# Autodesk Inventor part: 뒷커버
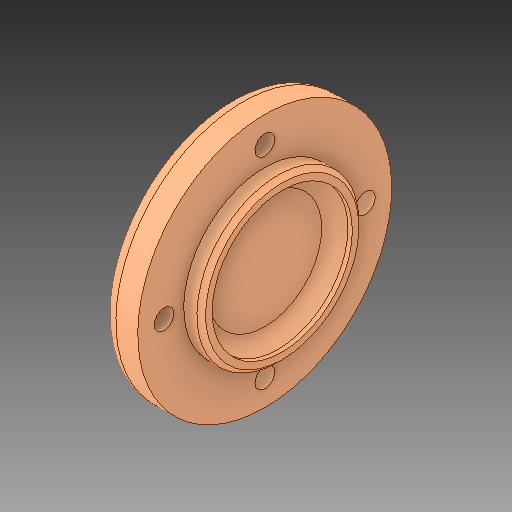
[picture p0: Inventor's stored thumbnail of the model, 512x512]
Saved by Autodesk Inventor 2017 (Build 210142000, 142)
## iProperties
Created: 2024-08
Part Number: 뒷커버
Material: 일반
Document SubType Name: Modeling
Designer: MRC
Density: 1 g/cm^3
Appearance: 기본값
Author: jhkim
Sending System: Autodesk Inventor 2025
Preprocessor: ST-DEVELOPER v20
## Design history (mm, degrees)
feature "솔리드1"
node "솔리드2"
